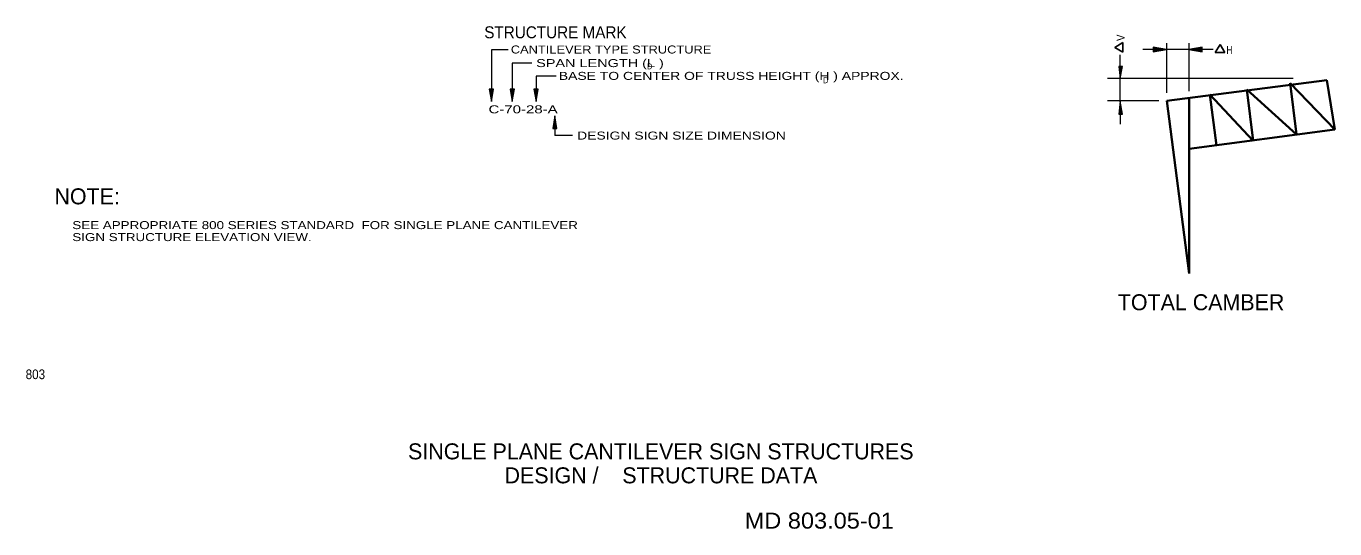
# Model space of a CAD drawing. Extents: x -34804.49 to -34794.67, y -181520.33 to -181510.37.
# Drawn here: x -34804.48 to -34794.67, y -181520.33 to -181516.55 of the extents above; entities that cross this region are included whole.
import ezdxf
from ezdxf.enums import TextEntityAlignment as Align

# ---------------------------------------------------------------- set-up
doc = ezdxf.new("R2010")
doc.units = 0
doc.header["$LTSCALE"] = 0.024
for name, color, linetype, lineweight in [('1', 7, 'Continuous', 13), ('10', 7, 'Continuous', 13), ('13', 7, 'Continuous', 25)]:
    doc.layers.add(name, color=color, linetype=linetype, lineweight=lineweight)

msp = doc.modelspace()

# ---------------------------------------------------------------- hatches: boundary and pattern name
at = {"layer": '10'}
for points in [[(-34796.036, -181516.711), (-34796.036, -181516.747), (-34795.937, -181516.729)], [(-34795.668, -181516.747), (-34795.668, -181516.711), (-34795.768, -181516.729)], [(-34796.266, -181516.856), (-34796.293, -181516.856), (-34796.284, -181516.946)], [(-34800.981, -181517.026), (-34801.013, -181517.026), (-34800.997, -181517.12)], [(-34800.824, -181517.026), (-34800.856, -181517.026), (-34800.84, -181517.12)], [(-34800.646, -181517.026), (-34800.678, -181517.026), (-34800.662, -181517.12)], [(-34796.293, -181517.214), (-34796.266, -181517.214), (-34796.284, -181517.116)], [(-34800.537, -181517.322), (-34800.505, -181517.322), (-34800.521, -181517.228)]]:
    msp.add_hatch(color=256, dxfattribs=at).paths.add_polyline_path(points)

# ---------------------------------------------------------------- linework, layer by layer
at = {"layer": '1', "lineweight": 35}
for p, q in [((-34795.934, -181517.114), (-34794.734, -181516.958)), ((-34794.962, -181517.366), (-34795.01, -181516.982)), ((-34794.674, -181517.33), (-34795.01, -181516.982)), ((-34794.674, -181517.33), (-34794.734, -181516.958)), ((-34795.766, -181518.41), (-34795.934, -181517.114)), ((-34795.766, -181518.41), (-34795.766, -181517.09)), ((-34795.562, -181517.45), (-34795.61, -181517.066)), ((-34795.286, -181517.414), (-34795.61, -181517.066)), ((-34795.286, -181517.414), (-34795.334, -181517.03)), ((-34794.962, -181517.366), (-34795.334, -181517.03)), ((-34795.766, -181517.474), (-34794.674, -181517.33))]:
    msp.add_line(p, q, dxfattribs=at)
at = {"layer": '10'}
for p, q in [((-34800.997, -181516.732), (-34800.997, -181517.12)), ((-34800.871, -181516.732), (-34800.997, -181516.732)), ((-34795.585, -181516.729), (-34796.114, -181516.729)), ((-34795.934, -181517.054), (-34795.934, -181516.681)), ((-34795.766, -181517.042), (-34795.766, -181516.681)), ((-34796.283, -181517.114), (-34796.283, -181516.769)), ((-34800.84, -181516.831), (-34800.84, -181517.12)), ((-34800.693, -181516.831), (-34800.84, -181516.831)), ((-34800.662, -181516.929), (-34800.662, -181517.12)), ((-34800.512, -181516.929), (-34800.662, -181516.929)), ((-34794.986, -181516.946), (-34796.379, -181516.946)), ((-34795.994, -181517.114), (-34796.379, -181517.114)), ((-34796.283, -181517.114), (-34796.283, -181517.29)), ((-34800.521, -181517.228), (-34800.521, -181517.375)), ((-34800.389, -181517.375), (-34800.521, -181517.375))]:
    msp.add_line(p, q, dxfattribs=at)
for points in [[(-34796.036, -181516.711), (-34796.036, -181516.747), (-34795.937, -181516.729)], [(-34795.668, -181516.747), (-34795.668, -181516.711), (-34795.768, -181516.729)], [(-34796.266, -181516.856), (-34796.293, -181516.856), (-34796.284, -181516.946)], [(-34800.981, -181517.026), (-34801.013, -181517.026), (-34800.997, -181517.12)], [(-34800.824, -181517.026), (-34800.856, -181517.026), (-34800.84, -181517.12)], [(-34800.646, -181517.026), (-34800.678, -181517.026), (-34800.662, -181517.12)], [(-34796.293, -181517.214), (-34796.266, -181517.214), (-34796.284, -181517.116)], [(-34800.537, -181517.322), (-34800.505, -181517.322), (-34800.521, -181517.228)]]:
    msp.add_lwpolyline(points, close=True, dxfattribs=at)
at = {"layer": '13'}
for p, q in [((-34796.262, -181516.749), (-34796.262, -181516.677)), ((-34795.57, -181516.751), (-34795.534, -181516.691)), ((-34795.534, -181516.691), (-34795.498, -181516.751)), ((-34795.57, -181516.751), (-34795.498, -181516.751))]:
    msp.add_line(p, q, dxfattribs=at)
msp.add_lwpolyline([(-34796.262, -181516.749), (-34796.322, -181516.713), (-34796.262, -181516.677)], dxfattribs=at)

# ---------------------------------------------------------------- texts
for s, height, width, p in [('STRUCTURE MARK', 0.09, 0.95, (-34801.05, -181516.645)), ('CANTILEVER TYPE STRUCTURE', 0.06, 1.2, (-34800.851, -181516.759)), ('H', 0.06, 0.75, (-34795.486, -181516.763)), ('SPAN LENGTH (L )', 0.06, 1.35, (-34800.661, -181516.861)), ('BASE TO CENTER OF TRUSS HEIGHT (H ) APPROX.', 0.06, 1.3, (-34800.491, -181516.957)), ('C-70-28-A', 0.06, 1.4, (-34801.018, -181517.208)), ('DESIGN SIGN SIZE DIMENSION', 0.06, 1.3, (-34800.354, -181517.405)), ('SEE APPROPRIATE 800 SERIES STANDARD  FOR SINGLE PLANE CANTILEVER', 0.06, 1.25, (-34804.138, -181518.077)), ('SIGN STRUCTURE ELEVATION VIEW.', 0.06, 1.25, (-34804.138, -181518.167)), ('MD 803.05-01', 0.12, 1.1, (-34799.098, -181520.325))]:
    msp.add_text(s, height=height, dxfattribs=dict(at, width=width)).set_placement(p)
at = {"layer": '13', "width": 0.9}
msp.add_text('V', height=0.06, rotation=90, dxfattribs=at).set_placement((-34796.25, -181516.665))
at = {"layer": '13'}
for s, height, width, p in [('D', 0.0449, 0.8, (-34799.8105, -181516.878)), ('D', 0.0449, 0.8, (-34798.4895, -181516.982)), ('803', 0.07251, 0.9, (-34804.415, -181519.203))]:
    msp.add_text(s, height=height, dxfattribs=dict(at, width=width)).set_placement(p, align=Align.CENTER)
msp.add_text('NOTE:', height=0.12, dxfattribs=at).set_placement((-34804.272, -181517.891))
for s, p in [('TOTAL CAMBER', (-34795.6765, -181518.686)), ('SINGLE PLANE CANTILEVER SIGN STRUCTURES', (-34799.7265, -181519.805)), ('DESIGN /    STRUCTURE DATA', (-34799.7255, -181519.985))]:
    msp.add_text(s, height=0.12, dxfattribs=at).set_placement(p, align=Align.CENTER)

doc.saveas('drawing.dxf')
